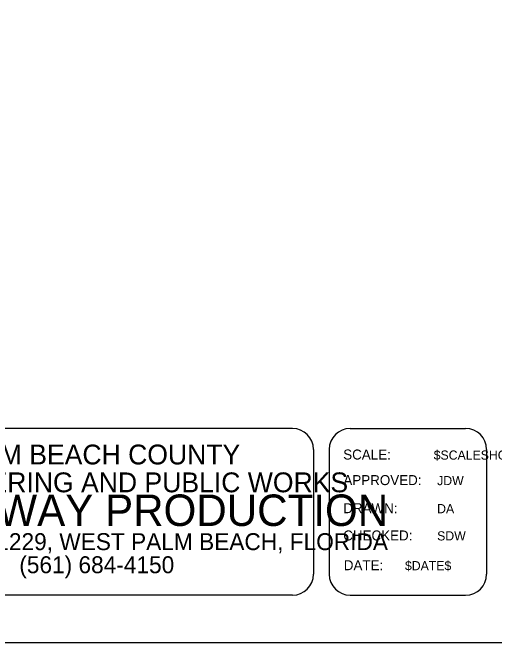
# Model space of a CAD drawing. Extents: x -0.6 to 16, y -0.9 to 9.7.
# Drawn here: x 9.999 to 12.024, y -0.9 to 1.75 of the extents above; entities that cross this region are included whole.
import ezdxf

# ---------------------------------------------------------------- set-up
doc = ezdxf.new("R2010")
doc.units = 0
doc.layers.add('Default', color=7, linetype='Continuous')
doc.layers.add('PlotBorder_dp', color=7, linetype='Continuous')

msp = doc.modelspace()

# ---------------------------------------------------------------- linework, layer by layer
at = {"layer": 'Default'}
for p, q in [((11.1756, 0), (8.7497, 0)), ((11.4182, 0), (11.9034, 0)), ((11.2638, -0.0882), (11.2638, -0.6131)), ((11.33, -0.0882), (11.33, -0.6131)), ((11.9916, -0.0882), (11.9916, -0.6131)), ((11.1756, -0.7014), (8.7497, -0.7014)), ((11.4182, -0.7014), (11.9034, -0.7014))]:
    msp.add_line(p, q, dxfattribs=at)
for centre, major_axis, start_param, end_param in [((11.1756, -0.0882), (0, 0.0882), 4.712389, 6.283185), ((11.4182, -0.0882), (0, 0.0882), 0, 1.570796), ((11.9034, -0.0882), (0, 0.0882), 4.712389, 6.283185), ((11.1756, -0.6131), (0, 0.0882), 3.141593, 4.712389), ((11.4182, -0.6131), (0, -0.0882), 4.712389, 6.283185), ((11.9034, -0.6131), (0, -0.0882), 0, 1.570796)]:
    msp.add_ellipse(centre, major_axis=major_axis, ratio=0.999927, start_param=start_param, end_param=end_param, dxfattribs=at)
at = {"layer": 'PlotBorder_dp'}
msp.add_lwpolyline([(-0.55, -0.9), (15.95, -0.9), (15.95, 9.7), (-0.55, 9.7)], close=True, dxfattribs=at)

# ---------------------------------------------------------------- texts
at = {"layer": 'Default'}
for s, height, p in [('PALM BEACH COUNTY', 0.083446, (9.7345, -0.1511)), ('ENGINEERING AND PUBLIC WORKS', 0.083468, (9.4745, -0.2683)), ('ROADWAY PRODUCTION', 0.132369, (9.4241, -0.4101)), ('P.O. BOX 21229, WEST PALM BEACH, FLORIDA', 0.071224, (9.4333, -0.5117)), ('(561) 684-4150', 0.071224, (10.0274, -0.6088))]:
    msp.add_text(s, height=height, rotation=360, dxfattribs=at).set_placement(p)
for s, height, p in [('SCALE:', 0.04207, (11.3888, -0.1305)), ('$SCALESHORT$', 0.038546, (11.7691, -0.1311)), ('APPROVED:', 0.04207, (11.3896, -0.2381)), ('JDW', 0.03855, (11.7836, -0.2384)), ('DRAWN:', 0.04207, (11.389, -0.3563)), ('DA ', 0.03855, (11.7836, -0.3565)), ('CHECKED:', 0.04207, (11.3889, -0.4711)), ('SDW', 0.03855, (11.7836, -0.471)), ('DATE:', 0.04207, (11.3913, -0.5963)), ('$DATE$', 0.03855, (11.6484, -0.5965))]:
    msp.add_text(s, height=height, dxfattribs=at).set_placement(p)

doc.saveas('drawing.dxf')
